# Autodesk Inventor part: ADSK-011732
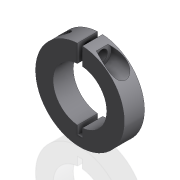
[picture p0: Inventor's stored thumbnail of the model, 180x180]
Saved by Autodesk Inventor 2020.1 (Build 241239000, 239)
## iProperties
Created: 1999-08
Part Number: ADSK-011732
Material: Pearson HRS
Description: COLLAR,SPLIT,SNGL,1.250
Document SubType Name: Modeling
Designer: MP
Density: 7.83 g/cm^3
Appearance: Métal - Acier
Mass: 117.829 g
Surface Area: 66.1172 cm^2
Volume: 15.0485 cm^3
Control State: 0
Master: False
Checked Out: False
Shininess: 0.0
Length Units: 11269
Angle Units: 11279
Time Units: 11290
Mass Units: 11283
Length Display Precision: 3
Angle Display Precision: 2
Compacted: True
Cutlength: 23.25
Material Desc: Material Description goes here
Material_Number: Pearson
Dimensions: 53x53x12 mm
Mass: 0,118 kg
DocNumber: ADSK-011732.ipt
Folder: 01 - Themengebiete\Simplification\01 - Packaging machine\
VDS_Category: 3D Komponenten
Density: 0.0
Volumn: 0.0
Area: 0.0
PropertySet Name: Model Information
Author: MP
Revision Number: -
Title: COLLAR,SPLIT,SNGL,1.250
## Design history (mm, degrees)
node "Extrusion2" dims "d5" = 25.4, "d6" = 0
  sketch "Sketch2"
    geometry: L1 (-1.5, -20.93)-(1.5, -20.93); L2 (1.5, -20.93)-(1.5, -15.93); L3 (-1.5, -20.93)-(-1.5, -15.93); L4 (0, 16)-(0, 16); L5 (-1.5, 15.93)-(1.5, 15.93); L6 (1.5, 15.93)-(1.5, 26.5); L7 (1.5, 26.5)-(-1.5, 26.5); L8 (-1.5, 26.5)-(-1.5, 15.93); L9 (0, -20.93)-(0, 26.5); A1 r 16 centre (0, 0) between (1.5, -15.93) and (-1.5, -15.93) reference; 1 further point
    constraints: 18 end point, 5 point on circle, 4 parallel, 2 midpoint, 2 perpendicular, 2 point on line, 1 horizontal, 1 tangent, 1 vertical, 1 vertical alignment, 1 other
    dimensions: "d4" = 3 distance of L1.start L1.end; "d19" = 5 distance of L1.start L3.end
node "Hole1" dims "d7" = 4.917, "d8" = 9.525, "d9" = 6.35, "d10" = 60 deg, "d11" = 17.1, "d12" = 118 deg, "d22" = 12
workplane "Work Plane1"
sketch "Sketch4"
  geometry: L1 (-26.458, 6)-(-26.458, -6) reference; 3 further points
  constraints: 1 horizontal alignment, 1 midpoint
node "Hole2" dims "d13" = 6.6, "d14" = 11, "d15" = 6.8, "d16" = 60 deg, "d17" = 26.19375, "d18" = 118 deg, "d23" = 6
node "Solide1"
  node "Extrusion1" dims "d2" = 12, "d3" = 0
sketch "Sketch1"
  geometry: C1 r 16 at (0, 0); C2 r 26.5 at (0, 0); 1 further point
  constraints: 2 centre point, 2 coincident
  dimensions: "d0" = 32 diameter of C1; "d1" = 53 diameter of C2
node "Corps solides"
node "Corps surfaciques"
sketch "Sketch3"
  geometry: L1 (0, 10.528)-(12, 10.528) reference; L2 (0, -42.43)-(0, 10.528) reference; 1 further point
  dimensions: "d20" = 6.35 distance from line of L2 point (6.35, 5.353); "d21" = 5.17509 distance from line of L1 point (6.35, 5.353)
other parameters: "d24" = 14
